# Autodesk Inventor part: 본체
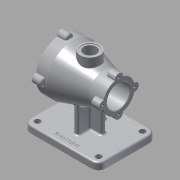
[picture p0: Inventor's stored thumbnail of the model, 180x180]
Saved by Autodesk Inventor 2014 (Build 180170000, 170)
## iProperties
Created: 2020-12
Part Number: 본체
Material: 알루미늄 6061
Document SubType Name: Modeling
Designer: kh
Density: 2.71 g/cm^3
Appearance: 알루미늄 - 평지
Mass: 1035.52 g
Surface Area: 855.157 cm^2
Volume: 382.11 cm^3
Author: kh
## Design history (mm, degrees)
sketch "스케치1"
  geometry: L1 (-65, -50)-(65, -50); L2 (65, -50)-(65, 50); L3 (65, 50)-(-65, 50); L4 (-65, 50)-(-65, -50); L5 (-65, -50)-(65, 50); L6 (65, -50)-(-65, 50); 1 further point
  constraints: 12 end point, 2 midpoint, 2 parallel, 1 horizontal, 1 perpendicular
  dimensions: "d0" = 130 distance of L1.start L1.end; "d1" = 100 distance of L1.end L2.end
extrude "돌출1" new body sketch "스케치1" distance "d2" = 12; taper "d3" = 0 deg
fillet "모깎기1" dims "d4" = 12
sketch "스케치2"
  geometry: 1 further point
sketch "스케치3"
  geometry: 1 further point
sketch "스케치4"
  geometry: L1 (-65, 38)-(-65, -38) reference; L2 (-53, -50)-(53, -50) reference; L3 (65, -38)-(65, 38) reference; L4 (53, 50)-(-53, 50) reference; C1 r 5 at (-53, 38); C2 r 5 at (53, 38); C3 r 5 at (53, -38); C4 r 5 at (-53, -38); A1 r 12 centre (-53, 38) between (-53, 50) and (-65, 38) reference; A2 r 12 centre (-53, -38) between (-65, -38) and (-53, -50) reference; A3 r 12 centre (53, -38) between (53, -50) and (65, -38) reference; A4 r 12 centre (53, 38) between (65, 38) and (53, 50) reference; 1 further point
  constraints: 4 centre point, 4 coincident
  dimensions: "d5" = 10 diameter of C1; "d6" = 10 diameter of C2; "d7" = 10 diameter of C4; "d8" = 10 diameter of C3
extrude "돌출2" cut sketch "스케치4" distance "d9" = 12; taper "d10" = 0 deg
sketch "스케치5"
  geometry: 1 further point
node "작업 평면1"
sketch "스케치6"
  geometry: L1 (0, 0)-(0, 82); C1 r 44 at (0, 82)
  constraints: 2 end point, 1 centre point, 1 coincident, 1 vertical
  dimensions: "d19" = 82 distance of L1.start L1.end; "d20" = 88 diameter of C1
extrude "돌출3" join sketch "스케치6" distance "d21" = 20; taper "d22" = 0 deg
node "작업 평면2"
sketch "스케치7"
  geometry: L1 (0, 0)-(0, 82); C1 r 27.5 at (0, 82)
  constraints: 2 end point, 1 centre point, 1 coincident, 1 vertical
  dimensions: "d24" = 82 distance of L1.start L1.end; "d25" = 55 diameter of C1
extrude "돌출4" join sketch "스케치7" distance "d26" = 25; taper "d27" = 0 deg
feature "로프트1" dims "d28" = 0, "d29" = 90 deg, "d30" = 0, "d31" = 90 deg
  node "모서리1"
  node "모서리2"
sketch "스케치8"
  geometry: C1 r 7 at (44, 0); C2 r 7 at (0, -44); C3 r 7 at (-44, 0); C4 r 7 at (0, 44); A1 r 44 centre (0, 0) between (44, 0) and (0, -44) reference; 1 further point
  constraints: 4 centre point, 4 point on circle
  dimensions: "d32" = 14 diameter of C1; "d33" = 14 diameter of C2; "d34" = 14 diameter of C3; "d35" = 14 diameter of C4
extrude "돌출5" join sketch "스케치8" distance "d36" = 15; taper "d37" = 0 deg
sketch "스케치9"
  geometry: C1 r 7 at (-27.5, 0); C2 r 7 at (0, 27.5); C3 r 7 at (27.5, 0); C4 r 7 at (0, -27.5); A1 r 27.5 centre (0, 0) between (-27.5, 0) and (0, 27.5) reference; 1 further point
  constraints: 4 centre point, 4 point on circle
  dimensions: "d38" = 14 diameter of C1; "d39" = 14 diameter of C2; "d40" = 14 diameter of C3; "d41" = 14 diameter of C4
extrude "돌출6" join sketch "스케치9" distance "d42" = 15; taper "d43" = 0 deg
fillet "모깎기2" dims "d44" = 1
fillet "모깎기3" dims "d45" = 3
fillet "모깎기4" dims "d46" = 1
fillet "모깎기5" dims "d47" = 3
fillet "모깎기6" dims "d48" = 3
sketch "스케치10"
  geometry: A1 r 44 centre (82, 0) between (89.817, -43.3) and (125.3, -7.817) reference; A2 r 44 centre (82, 0) between (125.3, 7.817) and (89.817, 43.3) reference; A3 r 7 centre (126, 0) between (126.249, -6.996) and (126.249, 6.996) reference; A4 r 7 centre (82, -44) between (75.004, -44.249) and (88.996, -44.249) reference; A5 r 7 centre (82, 44) between (88.996, 44.249) and (75.004, 44.249) reference; A6 r 7 centre (38, 0) between (37.751, 6.996) and (37.751, -6.996) reference; 5 further points
  constraints: 4 coincident
hole "구멍1" sketch "스케치10" at (126, 0), (82, -44), (38, 0), (82, 44) diameter "d49" = 4.134; stored, may be unused: countersink angle "d53" = 90 deg, drill point angle "d55" = 118 deg; dims "d50" = 9, "d51" = 4, "d52" = 2, "d54" = 11
sketch "스케치11"
  geometry: A1 r 7 centre (-109.5, 0) between (-109.373, 6.999) and (-109.373, -6.999) reference; A2 r 7 centre (-82, 27.5) between (-75.001, 27.373) and (-88.999, 27.373) reference; A3 r 7 centre (-54.5, 0) between (-54.627, -6.999) and (-54.627, 6.999) reference; A4 r 7 centre (-82, -27.5) between (-88.999, -27.373) and (-75.001, -27.373) reference; 5 further points
  constraints: 4 coincident
hole "구멍2" sketch "스케치11" at (-109.5, 0), (-82, 27.5), (-54.5, 0), (-82, -27.5) diameter "d56" = 4.134; stored, may be unused: countersink angle "d60" = 90 deg, drill point angle "d62" = 118 deg; dims "d57" = 9, "d58" = 4, "d59" = 2, "d61" = 11
node "작업 평면4"
sketch "스케치12"
  geometry: C1 r 17 at (0, 0); 1 further point
  constraints: 1 centre point, 1 coincident
  dimensions: "d65" = 34 diameter of C1
extrude "돌출7" join sketch "스케치12" stored distance "d66" = 15; taper "d67" = 0 deg
hole "구멍3" diameter "d70" = 64; stored, may be unused: countersink angle "d74" = 90 deg, drill point angle "d76" = 0 deg; dims "d68" = 10, "d69" = 10, "d71" = 9, "d72" = 4, "d73" = 2, "d75" = 23
hole "구멍4" diameter "d79" = 52; stored, may be unused: countersink angle "d83" = 90 deg, drill point angle "d85" = 0 deg; dims "d77" = 10, "d78" = 10, "d80" = 9, "d81" = 4, "d82" = 2, "d84" = 47
hole "구멍5" diameter "d88" = 40; stored, may be unused: countersink angle "d92" = 90 deg, drill point angle "d94" = 0 deg; dims "d86" = 10, "d87" = 10, "d89" = 9, "d90" = 4, "d91" = 2, "d93" = 30
sketch "스케치13"
  geometry: C1 r 14 at (0, 0); 1 further point
  constraints: 1 centre point, 1 coincident
  dimensions: "d95" = 28 diameter of C1
extrude "돌출8" cut sketch "스케치13" distance "d96" = 1; taper "d97" = 0 deg
sketch "스케치14"
  geometry: C1 r 11 at (0, 0); 1 further point
  constraints: 1 centre point, 1 coincident
  dimensions: "d98" = 22 diameter of C1
extrude "돌출9" cut sketch "스케치14" stored distance "d99" = 10; taper "d100" = 0 deg
sketch "스케치15"
  geometry: L1 (53, 12)-(-53, 12) reference; L2 (24, 12)-(24, 49.92); L3 (-24, 12)-(-24, 49.92); L4 (24, 49.92)-(24, 55); L5 (24, 55)-(-24, 55); L6 (-24, 55)-(-24, 49.92); L7 (24, 12)-(-24, 12); 1 further point
  constraints: 12 end point, 2 parallel, 2 perpendicular, 1 collinear, 1 point on line
extrude "돌출10" join sketch "스케치15" stored distance "d103" = 8; taper "d104" = 0 deg
sketch "스케치16"
  geometry: L1 (-25, 12)-(-25, 57); L2 (25, 12)-(25, 57); L3 (-25, 12)-(25, 12); L4 (-25, 57)-(-25, 65); L5 (-25, 65)-(25, 65); L6 (25, 65)-(25, 57); 5 further points
  constraints: 12 end point, 2 perpendicular, 1 parallel
extrude "돌출11" join sketch "스케치16" stored distance "d106" = 8; taper "d107" = 0 deg
hole "구멍6" diameter "d110" = 52; stored, may be unused: countersink angle "d114" = 90 deg, drill point angle "d116" = 0 deg; dims "d108" = 10, "d109" = 10, "d111" = 6, "d112" = 4, "d113" = 2, "d115" = 47
fillet "모깎기8" dims "d117" = 3
fillet "모깎기9" dims "d118" = 3
fillet "모깎기10" dims "d119" = 1
fillet "모깎기11" dims "d120" = 1
fillet "모깎기12" dims "d121" = 3
chamfer "모따기1" distance "d122" = 1; stored, may be unused: second distance "d123" = 2, angle "d124" = 45 deg
sketch "스케치17"
  geometry: 2 further points
  constraints: 1 other
feature "엠보싱1" sketch "스케치17" dims "d127" = 0.5, "d128" = 0
fillet "모깎기13" dims "d129" = 1
fillet "모깎기14" dims "d130" = 1
node "솔리드1"
